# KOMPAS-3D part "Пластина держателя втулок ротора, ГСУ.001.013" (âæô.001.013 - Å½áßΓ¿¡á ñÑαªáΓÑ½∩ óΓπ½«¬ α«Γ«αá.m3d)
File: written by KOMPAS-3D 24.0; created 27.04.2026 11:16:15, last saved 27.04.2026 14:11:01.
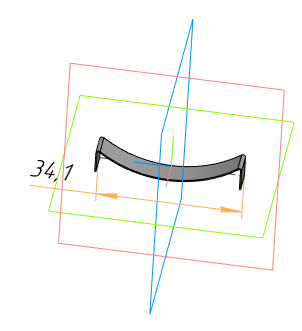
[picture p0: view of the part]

Document properties: Автор: User7; Полное имя файла: C:\Users\User7\Desktop\Двигатель мясорубки\ГСУ.001.013 - Пластина держателя втулок ротора.m3d

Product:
- Part/product: Пластина держателя втулок ротора  | designation ГСУ.001.013
    Масса: 0.000666

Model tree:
1. Эскиз:1
2. Листовое тело:1
     Расстояние 1 = 6; Толщина листового тела = 0.3; Радиус сгиба = 0.3; Радиус сгиба = 0.3; Коэффициент = 0.4; Величина сгиба = 10; Радиус сгиба = 26.7864; Коэффициент = 0.4; Величина сгиба = 10; Радиус сгиба = 0.3; Коэффициент = 0.4; Величина сгиба = 10
3. Линейный размер:1  (with: Грань.Листовое тело:1)
     Значение = 34.1

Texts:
  ГСУ.001.013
